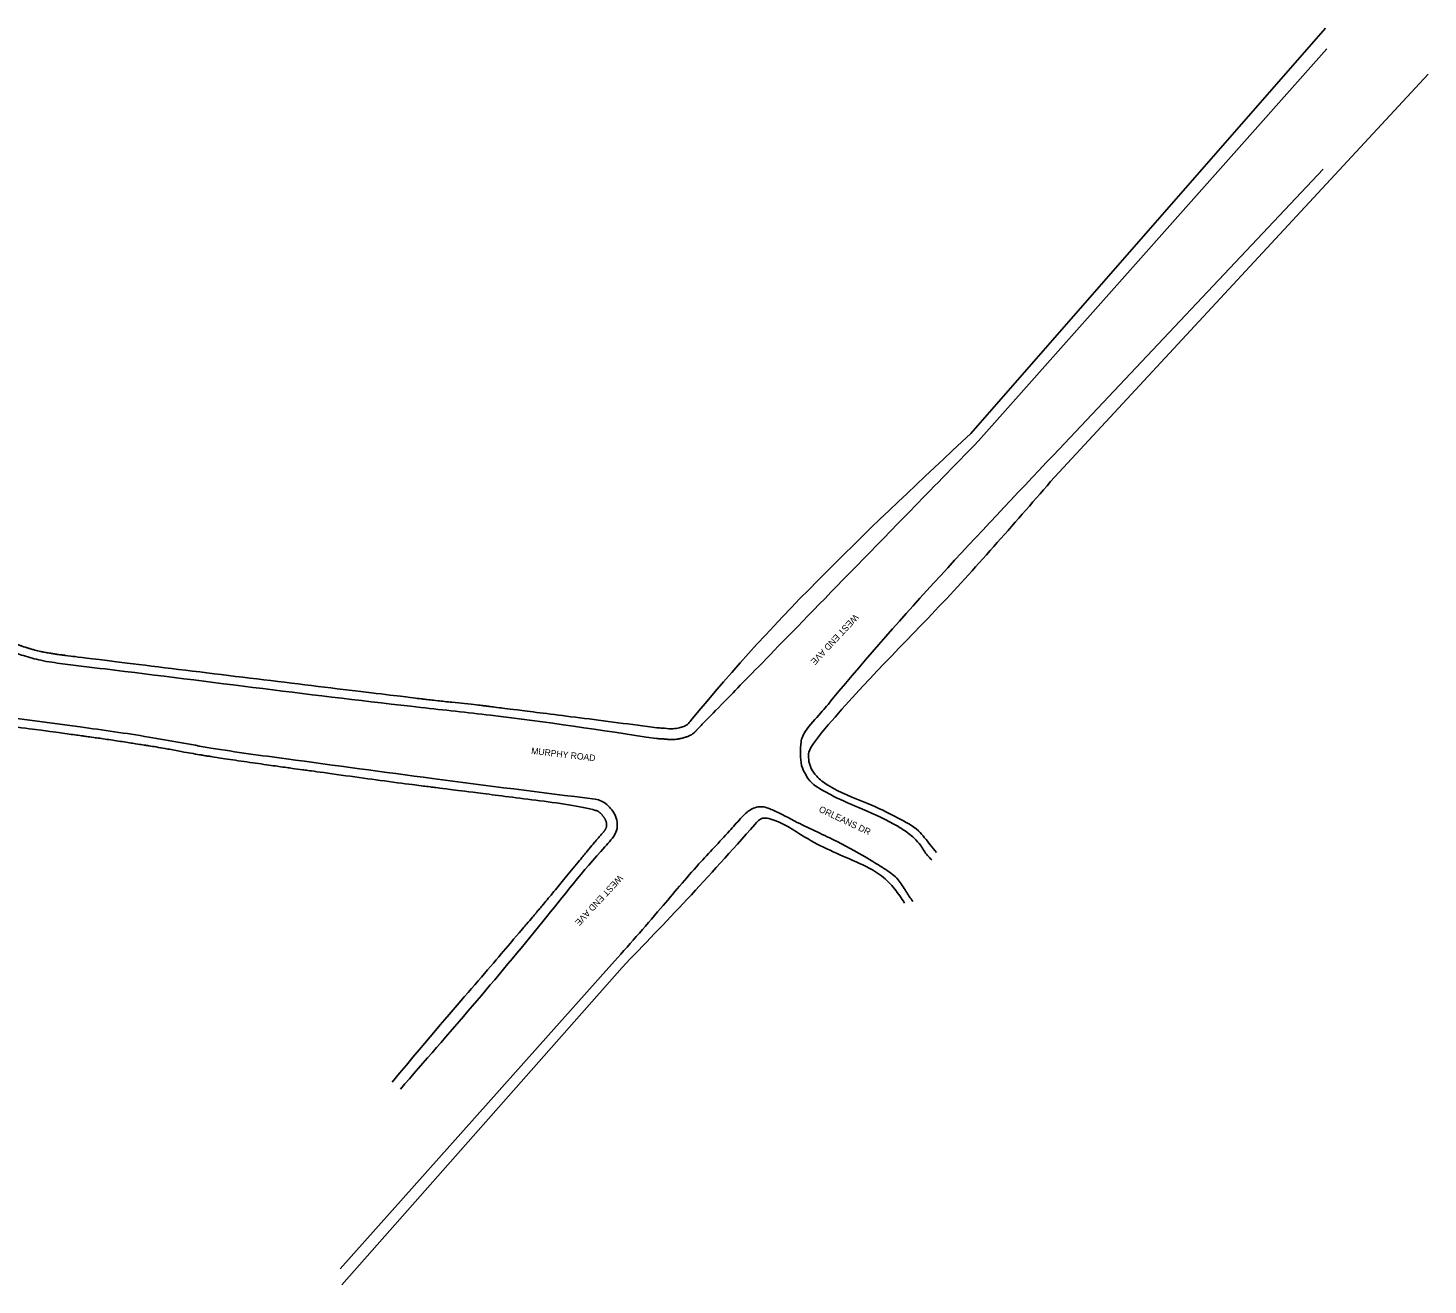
# Model space of a CAD drawing. Extents: x 1723992 to 1732080, y 650782 to 665122.
# Drawn here: x 1726106 to 1727410, y 657986 to 659157 of the extents above; entities that cross this region are included whole.
import ezdxf

# ---------------------------------------------------------------- set-up
doc = ezdxf.new("R2010")
doc.units = 0
for name, color, linetype in [('SURVEY - TRANSPORTATION - Features', 7, 'Continuous'), ('SURVEY - TRANSPORTATION - Roads', 7, 'Continuous'), ('SURVEY - TRANSPORTATION - Roads Text', 7, 'Continuous')]:
    doc.layers.add(name, color=color, linetype=linetype)

msp = doc.modelspace()

# ---------------------------------------------------------------- linework, layer by layer
at = {"layer": 'SURVEY - TRANSPORTATION - Features'}
for p, q in [((1726984.2539236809, 658779.5030082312), (1727314.6089970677, 659157.2596713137)), ((1727058.5938122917, 658734.5534278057), (1727410.27235602, 659114.1247192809)), ((1726659.2833074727, 658281.8738838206), (1726397.9439125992, 657985.85506819))]:
    msp.add_line(p, q, dxfattribs=at)
for points in [[(1725902.518390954, 658892.2674253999), (1725909.4536409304, 658872.438581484), (1725916.3640714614, 658852.609298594), (1725930.2529239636, 658812.9918526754), (1725937.243095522, 658793.200750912), (1725947.7530442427, 658763.510044), (1725952.1365952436, 658751.1387151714), (1725956.7375494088, 658738.14576833), (1725957.8327965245, 658735.0519864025), (1725958.2708756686, 658733.8144549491), (1725958.4905622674, 658733.1932578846), (1725959.1426109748, 658731.3534190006), (1725961.3286756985, 658725.2261715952), (1725965.3774027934, 658714.2441828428), (1725969.142086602, 658704.5329628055), (1725971.0969501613, 658699.6101674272), (1725971.126694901, 658699.5351895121), (1725971.1808645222, 658699.3993341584), (1725971.262500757, 658699.1955969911), (1725971.4556416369, 658698.7205160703), (1725971.8524169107, 658697.7714576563), (1725972.2100424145, 658696.9594691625), (1725972.9473858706, 658695.3364825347), (1725973.4684314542, 658694.2557985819), (1725975.108800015, 658691.010408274), (1725976.3057196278, 658688.8424213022), (1725978.8368320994, 658684.4611586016), (1725980.1709234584, 658682.2480540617), (1725981.7041031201, 658679.7104847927), (1725981.8648165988, 658679.4448740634), (1725982.191965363, 658678.9088277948), (1725982.68479528, 658678.1066061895), (1725983.8495347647, 658676.2471622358), (1725984.8734525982, 658674.6728172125), (1725986.9558909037, 658671.5453491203), (1725988.3903344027, 658669.48863585), (1725990.6131044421, 658666.427597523), (1725991.365875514, 658665.4112643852), (1725992.895376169, 658663.383650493), (1725993.6683269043, 658662.3790367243), (1726007.2298563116, 658644.9693845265), (1726020.8258279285, 658629.9454919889), (1726036.8879994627, 658616.0305155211), (1726037.3585176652, 658615.6270396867), (1726038.3145053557, 658614.819621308), (1726039.7529797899, 658613.6215822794), (1726041.206039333, 658612.4632729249), (1726044.1346622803, 658610.20076147), (1726046.1170272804, 658608.764589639), (1726050.1591068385, 658606.0418722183), (1726052.2188093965, 658604.7553038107), (1726054.4586117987, 658603.4703087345), (1726054.590554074, 658603.3950221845), (1726054.7887550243, 658603.2825453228), (1726054.8538255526, 658603.2457417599), (1726054.9941719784, 658603.1664538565), (1726055.345105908, 658602.968339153), (1726056.2584139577, 658602.4545954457), (1726058.230036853, 658601.3548408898), (1726062.1908664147, 658599.1805598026), (1726065.6145851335, 658597.3537828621), (1726070.2023873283, 658594.939513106), (1726072.5120127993, 658593.7393749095), (1726079.4287111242, 658590.1872621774), (1726084.0308258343, 658587.890702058), (1726089.246783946, 658585.4617576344), (1726090.116914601, 658585.0601479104), (1726090.9884437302, 658584.6636389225), (1726091.4244574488, 658584.4662576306), (1726091.5495810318, 658584.4099722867), (1726091.8155616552, 658584.2916110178), (1726093.0164020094, 658583.7623133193), (1726094.2526576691, 658583.2619900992), (1726097.628567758, 658581.9764730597), (1726099.985207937, 658581.1851582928), (1726103.0367470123, 658580.2028659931), (1726103.65485645, 658580.005731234), (1726104.8854879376, 658579.6155326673), (1726105.4980806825, 658579.4227442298), (1726107.3281693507, 658578.8535706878), (1726108.5379811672, 658578.4864022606), (1726112.1402268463, 658577.438948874), (1726114.5053059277, 658576.8131670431), (1726117.4282816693, 658576.1726088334), (1726118.1569562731, 658576.0212801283), (1726118.88334681, 658575.8818541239), (1726119.1011322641, 658575.8407531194), (1726119.1835348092, 658575.8252860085), (1726119.3417886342, 658575.7955900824), (1726119.7374102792, 658575.7214806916), (1726121.3987551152, 658575.4129727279), (1726125.5101310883, 658574.6768005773), (1726129.3016810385, 658574.0631557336), (1726133.0933527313, 658573.4992647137), (1726134.9892203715, 658573.2297565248), (1726137.2016846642, 658572.9383579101), (1726138.1500777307, 658572.8185419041), (1726138.7823897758, 658572.7398059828), (1726139.1102446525, 658572.6994669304), (1726142.04091825, 658572.3372856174), (1726165.4864585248, 658569.4410300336), (1726272.3000423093, 658556.2950458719), (1726379.137683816, 658543.3299053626), (1726466.439564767, 658532.7698916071), (1726470.3486193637, 658532.297117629), (1726472.9546590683, 658531.9819482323), (1726474.2434206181, 658531.8269565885), (1726480.7140418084, 658531.0640724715), (1726485.905687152, 658530.4891866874), (1726501.5186364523, 658528.8077602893), (1726511.9779716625, 658527.7447181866), (1726525.0903000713, 658526.2741946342), (1726529.0268575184, 658525.8223772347), (1726532.966981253, 658525.3484539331), (1726535.5944417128, 658525.0269093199), (1726536.9152667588, 658524.8617758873), (1726543.426392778, 658524.0404983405), (1726559.0530952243, 658522.069432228), (1726616.3510041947, 658514.8421898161), (1726668.4400123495, 658508.2719694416), (1726691.5598203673, 658505.0506942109)], [(1725915.695, 658526.927), (1725987.5759367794, 658520.2871152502), (1726047.5940461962, 658512.2509831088), (1726122.6241882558, 658502.1248646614), (1726137.630592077, 658500.0955949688), (1726154.5139152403, 658497.8129807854), (1726156.376134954, 658497.5591600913), (1726160.1124132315, 658497.0441951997), (1726165.7164202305, 658496.2641561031), (1726178.790013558, 658494.3941905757), (1726193.727779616, 658492.1580379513), (1726206.7988741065, 658490.1409668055), (1726212.868142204, 658489.1934919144), (1726215.2025970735, 658488.8275640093), (1726216.1363893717, 658488.6810765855), (1726216.6068229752, 658488.607354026), (1726217.9882101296, 658488.3897985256), (1726218.909446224, 658488.2421976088), (1726227.2037489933, 658486.8929208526), (1726234.5990274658, 658485.5447602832), (1726249.4776198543, 658482.8075083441), (1726256.96091866, 658481.4184196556), (1726266.3979517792, 658479.822978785), (1726269.2352852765, 658479.3549513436), (1726272.0827471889, 658478.9076228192), (1726273.5082319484, 658478.6878111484), (1726273.9718320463, 658478.6165819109), (1726274.9090425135, 658478.4725652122), (1726279.1265858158, 658477.8251727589), (1726298.3437841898, 658474.9039203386), (1726320.8625539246, 658471.6290696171), (1726339.6455396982, 658469.0195398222), (1726347.1601253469, 658467.9852599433), (1726350.9053903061, 658467.4720177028), (1726362.1541084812, 658465.923857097), (1726369.6541268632, 658464.8886957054), (1726407.1610901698, 658459.7161956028), (1726437.1886405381, 658455.5886994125), (1726471.030548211, 658451.2253139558), (1726474.7916063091, 658450.7443841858), (1726482.3155405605, 658449.7912398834), (1726486.070367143, 658449.3192793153), (1726497.3385872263, 658447.898669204), (1726519.875027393, 658445.0574489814), (1726572.460054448, 658438.4279351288), (1726617.5329347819, 658432.7454946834), (1726631.8912272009, 658428.8294375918)], [(1726631.8912272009, 658428.8294375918), (1726633.2918910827, 658428.5315885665), (1726634.6062678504, 658428.1631946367), (1726636.0486116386, 658427.642882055), (1726636.2083854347, 658427.5835744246), (1726636.4076408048, 658427.5074849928), (1726636.4602537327, 658427.4872055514), (1726636.4625348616, 658427.4863149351), (1726636.4673949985, 658427.4843837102), (1726636.4767363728, 658427.4804296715), (1726636.51835398, 658427.4617470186), (1726636.585816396, 658427.4287798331), (1726636.8930584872, 658427.2455836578), (1726637.2364688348, 658427.0063599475), (1726637.7980139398, 658426.5414675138), (1726637.9169657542, 658426.4405294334), (1726638.167546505, 658426.2233103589), (1726638.301796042, 658426.1047126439), (1726638.703448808, 658425.7445495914), (1726638.9609635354, 658425.5063032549), (1726639.7060268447, 658424.7933442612), (1726640.1659964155, 658424.3206889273), (1726640.8169184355, 658423.5960447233), (1726641.0274199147, 658423.3518182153), (1726641.4382740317, 658422.8539343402), (1726641.6426457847, 658422.5949621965), (1726642.2099311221, 658421.8427024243), (1726642.5268635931, 658421.3765029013), (1726643.1063793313, 658420.4249322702), (1726643.3700034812, 658419.9382043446), (1726643.6977532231, 658419.2484520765), (1726643.7631343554, 658419.1064515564), (1726643.8612925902, 658418.8862227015), (1726643.8940254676, 658418.8116092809), (1726643.9595640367, 658418.6597941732), (1726643.9800152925, 658418.6113474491), (1726644.0935907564, 658418.3355306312), (1726644.174021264, 658418.1173063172), (1726644.3896482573, 658417.461145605), (1726644.4998167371, 658417.0213620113), (1726644.6667267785, 658416.0927057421), (1726644.7230763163, 658415.603530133), (1726644.758998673, 658414.9426417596), (1726644.7645216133, 658414.8055270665), (1726644.7714074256, 658414.5439000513), (1726644.772820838, 658414.4184315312), (1726644.7713346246, 658414.0580175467), (1726644.7626818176, 658413.8391786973), (1726644.71805969, 658413.2432763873), (1726644.664576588, 658412.9294361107), (1726644.5615573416, 658412.5292201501), (1726644.5232242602, 658412.4068964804), (1726644.4571072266, 658412.2284038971), (1726644.4335885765, 658412.1697132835), (1726644.3953370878, 658412.0813154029), (1726644.3787755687, 658412.0444072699), (1726644.3613074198, 658412.0072018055), (1726644.356010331, 658411.9960193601), (1726644.3506256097, 658411.9846865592), (1726644.3410145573, 658411.9644944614), (1726644.316989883, 658411.9141044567), (1726643.9855956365, 658411.2248763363), (1726643.6619096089, 658410.6269505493), (1726643.0324048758, 658409.5758793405), (1726642.7073349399, 658409.0868603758), (1726642.1722868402, 658408.3551707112), (1726641.9859144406, 658408.1116487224), (1726641.6898874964, 658407.7414131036), (1726641.53775753, 658407.5550724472), (1726641.3521386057, 658407.3344970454), (1726641.2707499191, 658407.2391834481), (1726641.2297415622, 658407.1913882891), (1726641.217892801, 658407.1776104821), (1726641.1847627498, 658407.139169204), (1726640.1058216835, 658405.8884866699), (1726638.8761813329, 658404.5541838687), (1726636.9263064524, 658402.3680950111), (1726636.254673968, 658401.6030204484), (1726635.5299406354, 658400.7406040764), (1726635.4872693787, 658400.6896912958), (1726635.4232073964, 658400.6130446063), (1726635.399998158, 658400.5852283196), (1726635.3630443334, 658400.5409064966), (1726635.270661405, 658400.4301011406), (1726635.0304869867, 658400.1419968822), (1726634.5132969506, 658399.5214119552), (1726632.888515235, 658397.5706802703), (1726626.6930945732, 658390.1185686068), (1726620.8201427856, 658383.0101789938), (1726606.7461714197, 658365.9559814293), (1726597.391618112, 658354.5944761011), (1726585.6290960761, 658340.4929882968), (1726583.2731295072, 658337.6777070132), (1726579.7320407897, 658333.4639947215), (1726578.552097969, 658332.0632458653), (1726576.1810373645, 658329.2533664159), (1726570.249598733, 658322.2311464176), (1726564.3003302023, 658315.2203937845), (1726521.388414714, 658264.787664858), (1726482.6943448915, 658220.2774818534), (1726444.9107546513, 658174.8633518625)]]:
    msp.add_open_spline(points, degree=3, dxfattribs=at)
for points in [[(1726691.5598203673, 658505.0506942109), (1726696.6023722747, 658504.831299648), (1726704.9335449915, 658504.1731159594), (1726711.2915452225, 658504.831299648), (1726715.457131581, 658505.9282724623), (1726720.0612007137, 658508.3416126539), (1726723.349821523, 658511.8519256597), (1726984.2539236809, 658779.5030082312)], [(1726952.2172759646, 658389.0355349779), (1726946.4621895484, 658395.9464637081), (1726935.335689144, 658409.0004401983), (1726916.574331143, 658420.9837488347), (1726887.4197009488, 658434.9309746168), (1726850.9277550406, 658451.6178340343), (1726840.5685994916, 658460.0645247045), (1726835.0299580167, 658468.1401475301), (1726833.0791571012, 658475.5279236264), (1726833.3297186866, 658482.5485496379), (1726837.4639848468, 658490.4467539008), (1726845.1726686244, 658500.3782756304), (1726951.0662586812, 658614.4085996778), (1727058.5938122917, 658734.5534278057)], [(1726922.4825929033, 658341.7685994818), (1726913.2744546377, 658354.8225759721), (1726900.99693695, 658367.1086714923), (1726877.2092464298, 658380.1626479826), (1726829.63386539, 658403.1990770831), (1726795.8706917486, 658420.4763989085), (1726790.1156053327, 658420.8603393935), (1726782.8258292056, 658415.1012321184), (1726659.2833074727, 658281.8738838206)]]:
    msp.add_spline(points, degree=3, dxfattribs=at)
at = {"layer": 'SURVEY - TRANSPORTATION - Roads'}
for p, q in [((1726991.414669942, 658772.5227709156), (1727315.9563683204, 659137.7141461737)), ((1727061.162068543, 658759.1598292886), (1727312.4195187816, 659025.6643684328)), ((1726649.4704202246, 658284.5536841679), (1726396.5604510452, 658001.0076643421))]:
    msp.add_line(p, q, dxfattribs=at)
for points in [[(1725894.9669489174, 658889.6262659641), (1725918.5191124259, 658822.2873559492), (1725951.0435286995, 658730.2575122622), (1725963.68936965, 658696.5880572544), (1725974.813132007, 658675.6458089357), (1725987.7527074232, 658656.955825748), (1726031.4047007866, 658610.1965111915), (1726050.9361353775, 658596.2706413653), (1726068.6364979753, 658586.7424146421), (1726088.0458610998, 658577.2141879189), (1726101.227672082, 658572.3832700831), (1726117.5852485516, 658567.98562698), (1726137.7270404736, 658564.8095514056), (1726177.4002669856, 658559.9232812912), (1726471.4769856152, 658524.1023643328), (1726536.6326306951, 658516.8340375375), (1726691.1251452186, 658495.0601458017)], [(1726947.7154169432, 658382.0299503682), (1726943.6688718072, 658386.255377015), (1726940.5744117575, 658390.5549962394), (1726937.5676727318, 658395.3189924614), (1726931.3036330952, 658402.3396184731), (1726926.1671205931, 658406.6021414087), (1726912.5115141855, 658415.3779239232), (1726878.9143620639, 658431.0308969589), (1726853.3492502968, 658442.8311902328), (1726839.6936438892, 658450.8547628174), (1726835.6204276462, 658453.9868895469), (1726830.2975844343, 658461.5110701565), (1726827.2908454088, 658467.6541179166), (1726825.5369143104, 658477.808951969), (1726825.472683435, 658484.4827337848), (1726825.7874758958, 658489.9696791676), (1726826.9150030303, 658495.8619902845), (1726830.0470228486, 658501.8796697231), (1726844.366592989, 658518.9981998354), (1726855.1094209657, 658531.7230844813), (1727061.162068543, 658759.1598292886)], [(1725928.541, 658535.917), (1726154.0685235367, 658505.9459818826), (1726218.1009680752, 658496.4706022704), (1726275.9858093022, 658486.2863307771), (1726346.329413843, 658476.1754030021), (1726482.4085807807, 658457.8442552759), (1726633.9712041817, 658438.6107307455)], [(1726633.9712041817, 658438.6107307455), (1726640.0620564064, 658436.8160293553), (1726644.995913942, 658433.5333137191), (1726649.5060224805, 658428.7693174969), (1726653.1391654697, 658422.6262697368), (1726654.755703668, 658415.2123810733), (1726653.3897270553, 658407.7074394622), (1726648.7824944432, 658400.6371943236), (1726643.0687954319, 658394.1672934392), (1726585.4562171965, 658324.7390759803), (1726452.598086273, 658168.467655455)], [(1726649.4704202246, 658284.5536841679), (1726695.1274391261, 658336.769590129), (1726730.808974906, 658378.23516251), (1726759.2007345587, 658408.9504013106), (1726769.5598901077, 658420.4686158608), (1726778.0006835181, 658428.147425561), (1726788.359839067, 658431.602889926), (1726799.4863394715, 658428.5313660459), (1726822.4518747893, 658417.0131514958), (1726859.7229106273, 658399.0227973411), (1726891.2936703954, 658381.4712323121), (1726904.8866364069, 658372.9148443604), (1726916.5064299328, 658363.4808781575), (1726923.741395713, 658352.7305445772), (1726930.099395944, 658343.2965783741)]]:
    msp.add_spline(points, degree=3, dxfattribs=at)
msp.add_open_spline([(1726691.1251452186, 658495.0601458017), (1726692.2694434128, 658495.0103589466), (1726693.335580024, 658494.9773445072), (1726694.8160266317, 658494.9148928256), (1726695.2897154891, 658494.8920955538), (1726695.9705191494, 658494.8517320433), (1726696.1924612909, 658494.837203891), (1726696.6515865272, 658494.8045874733), (1726696.8856258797, 658494.7867282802), (1726698.0781711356, 658494.6908535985), (1726699.1035833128, 658494.5923755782), (1726701.2977242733, 658494.3937107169), (1726702.4665606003, 658494.2935002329), (1726703.8642554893, 658494.21386651), (1726704.0989282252, 658494.2013024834), (1726704.355963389, 658494.1890127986), (1726704.4552730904, 658494.1845118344), (1726704.4950329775, 658494.1827297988), (1726704.5261806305, 658494.1813573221), (1726704.6105510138, 658494.1778256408), (1726705.1151948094, 658494.1584664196), (1726705.6053425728, 658494.1551204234), (1726706.8757403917, 658494.1758816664), (1726707.673500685, 658494.2290066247), (1726709.9166585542, 658494.4476506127), (1726711.2133653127, 658494.6680536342), (1726712.4653636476, 658494.8849890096), (1726712.6696975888, 658494.9206261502), (1726712.8675507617, 658494.955193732), (1726712.9653974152, 658494.9722775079), (1726712.9912610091, 658494.9767553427), (1726713.0898089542, 658494.9940520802), (1726713.531957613, 658495.0727901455), (1726713.9621145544, 658495.1594062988), (1726715.0798454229, 658495.4043498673), (1726715.7855833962, 658495.5861214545), (1726717.1204685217, 658495.9633298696), (1726717.7497230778, 658496.1586860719), (1726718.4945571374, 658496.4002367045), (1726718.639134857, 658496.4475981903), (1726718.9463254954, 658496.5495154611), (1726719.1067560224, 658496.6034277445), (1726719.6077592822, 658496.7753875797), (1726719.9680380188, 658496.9035433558), (1726721.1222234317, 658497.3435268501), (1726721.9913074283, 658497.7091767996), (1726723.8821078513, 658498.7082316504), (1726724.9075453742, 658499.3453237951), (1726726.191942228, 658500.397616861), (1726726.4485434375, 658500.6206927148), (1726726.8299993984, 658500.9748872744), (1726726.9723941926, 658501.1113743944), (1726727.113708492, 658501.2519978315), (1726727.1372400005, 658501.2755115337), (1726727.1376431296, 658501.2759166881), (1726727.145626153, 658501.2839012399), (1726727.1655667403, 658501.303854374), (1726727.2171919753, 658501.3556248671), (1726727.515928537, 658501.6567503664), (1726727.781699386, 658501.9329578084), (1726728.4535695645, 658502.6431522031), (1726728.8525462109, 658503.0811230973), (1726729.5709610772, 658503.8691257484), (1726729.8904091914, 658504.219151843), (1726730.2475668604, 658504.5981148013), (1726730.3515313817, 658504.7074535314), (1726730.4591580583, 658504.8188695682), (1726730.4997640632, 658504.8606019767), (1726730.5159436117, 658504.8772055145), (1726730.5298497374, 658504.8914689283), (1726730.5646050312, 658504.9271229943), (1726730.7731367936, 658505.1410473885), (1726731.7231148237, 658506.1155918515), (1726735.615707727, 658510.1088472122), (1726751.18607934, 658526.0818686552), (1726789.7412852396, 658565.6341122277), (1726872.7832671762, 658650.8235599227), (1726943.9621088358, 658723.8430865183), (1726991.414669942, 658772.5227709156)], degree=3, dxfattribs=at)

# ---------------------------------------------------------------- texts
at = {"layer": 'SURVEY - TRANSPORTATION - Roads Text'}
for s, height, rotation, p in [('WEST END AVE', 5.9999999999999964, 227.05151538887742, (1726875.759442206, 658611.5375598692)), ('MURPHY ROAD ', 5.999999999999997, 353.3738378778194, (1726574.2391010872, 658480.813458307)), ('ORLEANS DR', 5.999999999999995, 334.71142662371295, (1726841.9986147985, 658427.1442521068)), ('WEST END AVE', 5.9999999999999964, 227.05151538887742, (1726656.1363178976, 658368.4740761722))]:
    msp.add_text(s, height=height, rotation=rotation, dxfattribs=at).set_placement(p)

doc.saveas('drawing.dxf')
